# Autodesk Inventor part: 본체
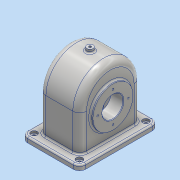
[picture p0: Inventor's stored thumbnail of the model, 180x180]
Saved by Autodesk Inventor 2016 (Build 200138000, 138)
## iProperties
Created: 2018-11
Part Number: 본체
Material: 알루미늄 6061
Document SubType Name: Modeling
Designer: user
Mass: 1092.08 g
Surface Area: 1182.21 cm^2
Volume: 404.475 cm^3
Density: 2.7 g/cm^3
Appearance: 알루미늄 - 평지
Author: user
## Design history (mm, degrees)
sketch "스케치1"
  geometry: L1 (-55, -75)-(55, -75); L2 (55, -75)-(55, 75); L3 (55, 75)-(-55, 75); L4 (-55, 75)-(-55, -75); L5 (-55, -75)-(55, 75); L6 (55, -75)-(-55, 75); 1 further point
  constraints: 12 end point, 2 midpoint, 2 parallel, 1 horizontal, 1 perpendicular
  dimensions: "d0" = 110 distance of L3.end L2.end; "d1" = 150 distance of L2.end L1.end
extrude "돌출1" new body sketch "스케치1" distance "d2" = 10; taper "d3" = 0 deg
sketch "스케치2"
  geometry: L1 (38.5, 58)-(-38.5, 58); L2 (-38.5, 58)-(-38.5, -58); L3 (-38.5, -58)-(38.5, -58); L4 (38.5, -58)-(38.5, 58); L5 (38.5, 58)-(-38.5, -58); L6 (-38.5, 58)-(38.5, -58); 1 further point
  constraints: 12 end point, 2 midpoint, 2 parallel, 1 horizontal, 1 perpendicular
  dimensions: "d4" = 77 distance of L3.end L2.end; "d5" = 116 distance of L1.end L2.end
extrude "돌출2" join sketch "스케치2" distance "d6" = 126; taper "d7" = 0 deg
fillet "모깎기1" dims "d8" = 58
feature "쉘1" dims "d10" = 10, "d11" = 5, "d27" = 6
node "작업 평면1"
sketch "스케치3"
  geometry: C1 r 6 at (0, 0); 1 further point
  constraints: 1 centre point, 1 coincident
  dimensions: "d13" = 12 diameter of C1
extrude "돌출3" join sketch "스케치3" stored distance "d14" = 126; taper "d15" = 5 deg
sketch "스케치7"
  geometry: L1 (10, -17)-(10, 133) reference; C1 r 38 at (-55, 58); 2 further points
  constraints: 1 centre point, 1 horizontal alignment, 1 midpoint
  dimensions: "d28" = 76 diameter of C1; "d29" = 65 distance from line of L1 C1.centre
extrude "돌출7" join sketch "스케치7" distance "d30" = 5; taper "d31" = 0 deg
sketch "스케치8"
  geometry: L1 (-10, 133)-(-10, -17) reference; C1 r 38 at (55, 58); 2 further points
  constraints: 1 centre point, 1 horizontal alignment, 1 midpoint
  dimensions: "d32" = 76 diameter of C1; "d33" = 65 distance from line of L1 C1.centre
extrude "돌출8" join sketch "스케치8" distance "d34" = 10; taper "d35" = 0 deg
node "작업 평면2"
sketch "스케치10"
  geometry: C1 r 28 at (0, 0); 1 further point
  constraints: 1 centre point, 1 vertical alignment
  dimensions: "d40" = 56 diameter of C1; "d41" = 65 distance of point (0, -65) C1.centre
extrude "돌출10" join sketch "스케치10" distance "d42" = 14; taper "d43" = 40 deg
sketch "스케치9"
  geometry: C1 r 20 at (0, 0); C2 r 38 at (0, 0) reference; 1 further point
  constraints: 1 centre point, 1 concentric
  dimensions: "d36" = 40 diameter of C1
extrude "돌출9" cut sketch "스케치9" stored distance "d37" = 10; taper "d38" = 0 deg
sketch "스케치11"
  geometry: L1 (65, -75)-(65, 75) reference; C1 r 20 at (0, 0) reference; 3 further points
  constraints: 1 horizontal alignment, 1 midpoint
  dimensions: "d44" = 29 distance of C1.centre point (-29, 0)
hole "구멍1" sketch "스케치11" at (-29, 0) diameter "d45" = 3.242; stored, may be unused: countersink angle "d49" = 90 deg, drill point angle "d51" = 118 deg; dims "d46" = 8, "d47" = 4, "d48" = 2, "d50" = 10
sketch "스케치12"
  geometry: L1 (-65, 75)-(-65, -75) reference; C1 r 20 at (0, 0) reference; 3 further points
  constraints: 1 horizontal alignment, 1 midpoint
  dimensions: "d55" = 29 distance of C1.centre point (29, 0)
hole "구멍2" sketch "스케치12" at (29, 0) diameter "d56" = 3.242; stored, may be unused: countersink angle "d60" = 90 deg, drill point angle "d62" = 118 deg; dims "d57" = 8, "d58" = 4, "d59" = 2, "d61" = 10
sketch "스케치13"
  geometry: 2 further points
  constraints: 1 coincident
hole "구멍3" sketch "스케치13" at (0, 0) diameter "d66" = 4.459; stored, may be unused: countersink angle "d70" = 90 deg, drill point angle "d72" = 118 deg; dims "d67" = 30, "d68" = 4, "d69" = 2, "d71" = 34.95
fillet "모깎기3" dims "d73" = 12
fillet "모깎기4" dims "d74" = 3
sketch "스케치14"
  geometry: A1 r 12 centre (43, -63) between (43, -75) and (55, -63) reference; A2 r 9 centre (-43, -63) between (-52, -63) and (-43, -72) reference; A3 r 12 centre (-43, 63) between (-43, 75) and (-55, 63) reference; A4 r 12 centre (43, 63) between (55, 63) and (43, 75) reference; 5 further points
  constraints: 4 coincident
hole "구멍4" sketch "스케치14" at (43, -63), (-43, -63), (-43, 63), (43, 63) diameter "d75" = 5; stored, may be unused: countersink angle "d79" = 90 deg, drill point angle "d81" = 118 deg; dims "d76" = 30, "d77" = 12, "d78" = 4, "d80" = 34.95
fillet "모깎기5" dims "d82" = 13
fillet "모깎기6" dims "d83" = 3
chamfer "모따기1" distance "d84" = 1; stored, may be unused: second distance "d85" = 2, angle "d86" = 45 deg
fillet "모깎기7" dims "d87" = 8
fillet "모깎기8" dims "d88" = 3
sketch "스케치16"
  geometry: L1 (64, 0)-(64, 65) reference; L2 (68.5, 78)-(-17.5, 78) reference; 2 further points
  constraints: 1 other
  dimensions: "d92" = 38.5 distance from line of point (25.5, 38) L1; "d93" = 40 distance from line of L2 point (25.5, 38)
feature "엠보싱2" sketch "스케치16" dims "d0" = 110, "d1" = 150, "d94" = 0.5, "d95" = 0
node "솔리드1"
pattern_circular "원형 패턴1" dims angle "d53" = 360 deg
pattern_circular "원형 패턴2" dims angle "d64" = 360 deg
other parameters: "d12" = 142, "d39" = -24
